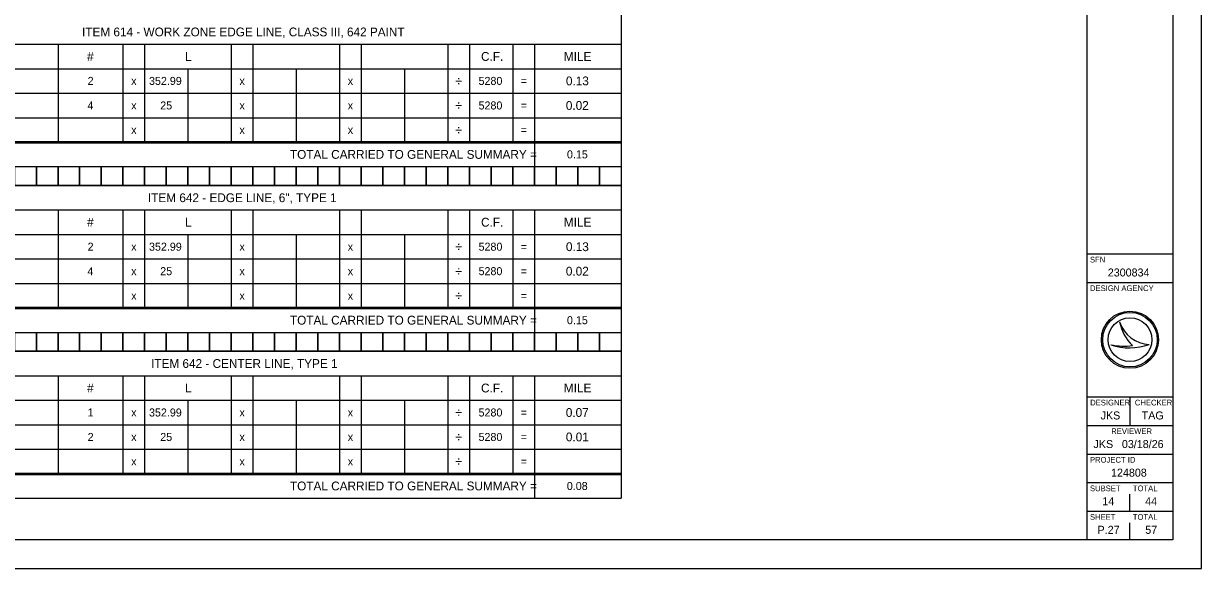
# Model space of a CAD drawing. Extents: x 0 to 34, y 0 to 22.
# Drawn here: x 13.4 to 34, y 0 to 9.53 of the extents above; entities that cross this region are included whole.
import ezdxf

# ---------------------------------------------------------------- set-up
doc = ezdxf.new("R2010")
doc.units = 0
for name, color, linetype in [('Default', 7, 'Continuous'), ('SH_Border', 7, 'Continuous'), ('SH_Cut_Line', 7, 'Continuous'), ('SH_Data', 7, 'Continuous')]:
    doc.layers.add(name, color=color, linetype=linetype)

msp = doc.modelspace()

# ---------------------------------------------------------------- linework, layer by layer
at = {"layer": 'Default'}
for p, q in [((23.849, 10.364), (23.849, 7.443)), ((10.59, 9.167), (23.849, 9.167)), ((14, 9.167), (14, 7.465)), ((15.136, 9.167), (15.136, 7.465)), ((15.515, 9.167), (15.515, 7.465)), ((17.03, 9.167), (17.03, 7.465)), ((17.409, 9.167), (17.409, 7.465)), ((18.924, 9.167), (18.924, 7.465)), ((19.303, 9.167), (19.303, 7.465)), ((20.818, 9.167), (20.818, 7.465)), ((21.197, 9.167), (21.197, 7.465)), ((21.955, 9.167), (21.955, 7.465)), ((22.334, 9.167), (22.334, 7.465)), ((10.59, 8.739), (23.849, 8.739)), ((16.272, 8.739), (16.272, 7.465)), ((18.167, 8.739), (18.167, 7.465)), ((20.061, 8.739), (20.061, 7.465)), ((10.59, 8.311), (23.849, 8.311)), ((10.59, 7.882), (23.849, 7.882)), ((10.59, 7.465), (23.849, 7.465)), ((10.59, 7.443), (23.849, 7.443)), ((22.334, 7.443), (22.334, 7.026)), ((23.849, 7.465), (23.849, 4.544)), ((10.59, 7.026), (23.849, 7.026)), ((10.59, 6.696), (23.849, 6.696)), ((10.59, 6.268), (23.849, 6.268)), ((14, 6.268), (14, 4.566)), ((15.136, 6.268), (15.136, 4.566)), ((15.515, 6.268), (15.515, 4.566)), ((17.03, 6.268), (17.03, 4.566)), ((17.409, 6.268), (17.409, 4.566)), ((18.924, 6.268), (18.924, 4.566)), ((19.303, 6.268), (19.303, 4.566)), ((20.818, 6.268), (20.818, 4.566)), ((21.197, 6.268), (21.197, 4.566)), ((21.955, 6.268), (21.955, 4.566)), ((22.334, 6.268), (22.334, 4.566)), ((10.59, 5.84), (23.849, 5.84)), ((16.272, 5.84), (16.272, 4.566)), ((18.167, 5.84), (18.167, 4.566)), ((20.061, 5.84), (20.061, 4.566)), ((10.59, 5.412), (23.849, 5.412)), ((10.59, 4.983), (23.849, 4.983)), ((10.59, 4.566), (23.849, 4.566)), ((10.59, 4.544), (23.849, 4.544)), ((22.334, 4.544), (22.334, 4.127)), ((23.849, 4.566), (23.849, 1.645)), ((10.59, 4.127), (23.849, 4.127)), ((10.59, 3.798), (23.849, 3.798)), ((10.59, 3.369), (23.849, 3.369)), ((14, 3.369), (14, 1.667)), ((15.136, 3.369), (15.136, 1.667)), ((15.515, 3.369), (15.515, 1.667)), ((17.03, 3.369), (17.03, 1.667)), ((17.409, 3.369), (17.409, 1.667)), ((18.924, 3.369), (18.924, 1.667)), ((19.303, 3.369), (19.303, 1.667)), ((20.818, 3.369), (20.818, 1.667)), ((21.197, 3.369), (21.197, 1.667)), ((21.955, 3.369), (21.955, 1.667)), ((22.334, 3.369), (22.334, 1.667)), ((10.59, 2.941), (23.849, 2.941)), ((16.272, 2.941), (16.272, 1.667)), ((18.167, 2.941), (18.167, 1.667)), ((20.061, 2.941), (20.061, 1.667)), ((10.59, 2.513), (23.849, 2.513)), ((10.59, 2.085), (23.849, 2.085)), ((10.59, 1.667), (23.849, 1.667)), ((23.849, 1.667), (23.849, 1.228)), ((10.59, 1.645), (23.849, 1.645)), ((22.334, 1.645), (22.334, 1.228)), ((10.59, 1.228), (23.849, 1.228))]:
    msp.add_line(p, q, dxfattribs=at)
for points in [[(13.242, 7.026), (13.621, 7.026), (13.621, 6.696), (13.242, 6.696)], [(13.621, 7.026), (14, 7.026), (14, 6.696), (13.621, 6.696)], [(14, 7.026), (14.378, 7.026), (14.378, 6.696), (14, 6.696)], [(14.378, 7.026), (14.757, 7.026), (14.757, 6.696), (14.378, 6.696)], [(14.757, 7.026), (15.136, 7.026), (15.136, 6.696), (14.757, 6.696)], [(15.136, 7.026), (15.515, 7.026), (15.515, 6.696), (15.136, 6.696)], [(15.515, 7.026), (15.894, 7.026), (15.894, 6.696), (15.515, 6.696)], [(15.894, 7.026), (16.272, 7.026), (16.272, 6.696), (15.894, 6.696)], [(16.272, 7.026), (16.651, 7.026), (16.651, 6.696), (16.272, 6.696)], [(16.651, 7.026), (17.03, 7.026), (17.03, 6.696), (16.651, 6.696)], [(17.03, 7.026), (17.409, 7.026), (17.409, 6.696), (17.03, 6.696)], [(17.409, 7.026), (17.788, 7.026), (17.788, 6.696), (17.409, 6.696)], [(17.788, 7.026), (18.167, 7.026), (18.167, 6.696), (17.788, 6.696)], [(18.167, 7.026), (18.545, 7.026), (18.545, 6.696), (18.167, 6.696)], [(18.545, 7.026), (18.924, 7.026), (18.924, 6.696), (18.545, 6.696)], [(18.924, 7.026), (19.303, 7.026), (19.303, 6.696), (18.924, 6.696)], [(19.303, 7.026), (19.682, 7.026), (19.682, 6.696), (19.303, 6.696)], [(19.682, 7.026), (20.061, 7.026), (20.061, 6.696), (19.682, 6.696)], [(20.061, 7.026), (20.44, 7.026), (20.44, 6.696), (20.061, 6.696)], [(20.44, 7.026), (20.818, 7.026), (20.818, 6.696), (20.44, 6.696)], [(20.818, 7.026), (21.197, 7.026), (21.197, 6.696), (20.818, 6.696)], [(21.197, 7.026), (21.576, 7.026), (21.576, 6.696), (21.197, 6.696)], [(21.576, 7.026), (21.955, 7.026), (21.955, 6.696), (21.576, 6.696)], [(21.955, 7.026), (22.334, 7.026), (22.334, 6.696), (21.955, 6.696)], [(22.334, 7.026), (22.712, 7.026), (22.712, 6.696), (22.334, 6.696)], [(22.712, 7.026), (23.091, 7.026), (23.091, 6.696), (22.712, 6.696)], [(23.091, 7.026), (23.47, 7.026), (23.47, 6.696), (23.091, 6.696)], [(23.47, 7.026), (23.849, 7.026), (23.849, 6.696), (23.47, 6.696)], [(13.242, 4.127), (13.621, 4.127), (13.621, 3.798), (13.242, 3.798)], [(13.621, 4.127), (14, 4.127), (14, 3.798), (13.621, 3.798)], [(14, 4.127), (14.378, 4.127), (14.378, 3.798), (14, 3.798)], [(14.378, 4.127), (14.757, 4.127), (14.757, 3.798), (14.378, 3.798)], [(14.757, 4.127), (15.136, 4.127), (15.136, 3.798), (14.757, 3.798)], [(15.136, 4.127), (15.515, 4.127), (15.515, 3.798), (15.136, 3.798)], [(15.515, 4.127), (15.894, 4.127), (15.894, 3.798), (15.515, 3.798)], [(15.894, 4.127), (16.272, 4.127), (16.272, 3.798), (15.894, 3.798)], [(16.272, 4.127), (16.651, 4.127), (16.651, 3.798), (16.272, 3.798)], [(16.651, 4.127), (17.03, 4.127), (17.03, 3.798), (16.651, 3.798)], [(17.03, 4.127), (17.409, 4.127), (17.409, 3.798), (17.03, 3.798)], [(17.409, 4.127), (17.788, 4.127), (17.788, 3.798), (17.409, 3.798)], [(17.788, 4.127), (18.167, 4.127), (18.167, 3.798), (17.788, 3.798)], [(18.167, 4.127), (18.545, 4.127), (18.545, 3.798), (18.167, 3.798)], [(18.545, 4.127), (18.924, 4.127), (18.924, 3.798), (18.545, 3.798)], [(18.924, 4.127), (19.303, 4.127), (19.303, 3.798), (18.924, 3.798)], [(19.303, 4.127), (19.682, 4.127), (19.682, 3.798), (19.303, 3.798)], [(19.682, 4.127), (20.061, 4.127), (20.061, 3.798), (19.682, 3.798)], [(20.061, 4.127), (20.44, 4.127), (20.44, 3.798), (20.061, 3.798)], [(20.44, 4.127), (20.818, 4.127), (20.818, 3.798), (20.44, 3.798)], [(20.818, 4.127), (21.197, 4.127), (21.197, 3.798), (20.818, 3.798)], [(21.197, 4.127), (21.576, 4.127), (21.576, 3.798), (21.197, 3.798)], [(21.576, 4.127), (21.955, 4.127), (21.955, 3.798), (21.576, 3.798)], [(21.955, 4.127), (22.334, 4.127), (22.334, 3.798), (21.955, 3.798)], [(22.334, 4.127), (22.712, 4.127), (22.712, 3.798), (22.334, 3.798)], [(22.712, 4.127), (23.091, 4.127), (23.091, 3.798), (22.712, 3.798)], [(23.091, 4.127), (23.47, 4.127), (23.47, 3.798), (23.091, 3.798)], [(23.47, 4.127), (23.849, 4.127), (23.849, 3.798), (23.47, 3.798)]]:
    msp.add_lwpolyline(points, close=True, dxfattribs=at)
at = {"layer": 'SH_Border'}
for p, q in [((32, 0.5), (32, 21.5)), ((32, 5.5), (33.5, 5.5)), ((32, 5), (33.5, 5)), ((32, 3), (33.5, 3)), ((32.75, 3), (32.75, 2.5)), ((32, 2.5), (33.5, 2.5)), ((32, 2), (33.5, 2)), ((32, 1.5), (33.5, 1.5)), ((32, 1), (33.5, 1))]:
    msp.add_line(p, q, dxfattribs=at)
msp.add_lwpolyline([(1.5, 21.5), (33.5, 21.5), (33.5, 0.5), (1.5, 0.5)], close=True, dxfattribs=at)
at = {"layer": 'SH_Cut_Line'}
msp.add_lwpolyline([(0, 0), (34, 0), (34, 22), (0, 22)], close=True, dxfattribs=at)
at = {"layer": 'SH_Data'}
for p, q in [((32.567, 4.31), (32.567, 4.31)), ((32.75, 4), (32.75, 4)), ((33.087, 3.919), (33.087, 3.919)), ((32.417, 3.91), (32.417, 3.91)), ((32.75, 1), (32.75, 1.3)), ((32.375, 0.675), (32.375, 0.675)), ((32.75, 0.5), (32.75, 0.8))]:
    msp.add_line(p, q, dxfattribs=at)
for radius in [0.5, 0.477, 0.477, 0.382]:
    msp.add_circle((32.75, 4), radius, dxfattribs=at)
for centre, radius, start, end in [((33.116, 4.498), 0.58, 198.9257, 198.9319), ((33.347, 4.47), 0.796, 191.6379, 191.6421), ((33.116, 4.498), 0.58, 198.9319, 267.1657), ((33.347, 4.47), 0.796, 191.6421, 226.0947), ((32.739, 4.87), 1.013, 251.4576, 290.0832), ((32.648, 5.154), 1.266, 259.4964, 259.4995), ((32.739, 4.87), 1.013, 251.4527, 251.4576), ((32.648, 5.154), 1.266, 259.4995, 276.6672)]:
    msp.add_arc(centre, radius, start, end, dxfattribs=at)

# ---------------------------------------------------------------- texts
at = {"layer": 'Default'}
for s, height, p in [('ITEM 614 - WORK ZONE EDGE LINE, CLASS III, 642 PAINT', 0.154, (14.42, 9.304)), ('#', 0.154, (14.509, 8.876)), ('L', 0.154, (16.222, 8.876)), ('C.F.', 0.154, (21.399, 8.876)), ('MILE', 0.154, (22.848, 8.876)), ('2', 0.14, (14.518, 8.455)), ('x', 0.14, (15.28, 8.455)), ('352.99', 0.14, (15.592, 8.455)), ('x', 0.14, (17.174, 8.455)), ('x', 0.14, (19.068, 8.455)), ('÷', 0.168, (20.946, 8.441)), ('5280', 0.14, (21.356, 8.455)), ('=', 0.14, (22.094, 8.455)), ('0.13', 0.154, (22.884, 8.448)), ('4', 0.14, (14.515, 8.026)), ('x', 0.14, (15.28, 8.026)), ('25', 0.14, (15.788, 8.026)), ('x', 0.14, (17.174, 8.026)), ('x', 0.14, (19.068, 8.026)), ('÷', 0.168, (20.946, 8.012)), ('5280', 0.14, (21.356, 8.026)), ('=', 0.14, (22.094, 8.026)), ('0.02', 0.154, (22.883, 8.019)), ('x', 0.14, (15.28, 7.598)), ('x', 0.14, (17.174, 7.598)), ('x', 0.14, (19.068, 7.598)), ('÷', 0.168, (20.946, 7.584)), ('=', 0.14, (22.094, 7.598)), ('TOTAL CARRIED TO GENERAL SUMMARY =', 0.154, (18.057, 7.163)), ('0.15', 0.14, (22.902, 7.17)), ('ITEM 642 - EDGE LINE, 6", TYPE 1', 0.154, (15.573, 6.405)), ('#', 0.154, (14.509, 5.977)), ('L', 0.154, (16.222, 5.977)), ('C.F.', 0.154, (21.399, 5.977)), ('MILE', 0.154, (22.848, 5.977)), ('2', 0.14, (14.518, 5.556)), ('x', 0.14, (15.28, 5.556)), ('352.99', 0.14, (15.592, 5.556)), ('x', 0.14, (17.174, 5.556)), ('x', 0.14, (19.068, 5.556)), ('÷', 0.168, (20.946, 5.542)), ('5280', 0.14, (21.356, 5.556)), ('=', 0.14, (22.094, 5.556)), ('0.13', 0.154, (22.884, 5.549)), ('4', 0.14, (14.515, 5.128)), ('x', 0.14, (15.28, 5.128)), ('25', 0.14, (15.788, 5.128)), ('x', 0.14, (17.174, 5.128)), ('x', 0.14, (19.068, 5.128)), ('÷', 0.168, (20.946, 5.114)), ('5280', 0.14, (21.356, 5.128)), ('=', 0.14, (22.094, 5.128)), ('0.02', 0.154, (22.883, 5.121)), ('x', 0.14, (15.28, 4.699)), ('x', 0.14, (17.174, 4.699)), ('x', 0.14, (19.068, 4.699)), ('÷', 0.168, (20.946, 4.685)), ('=', 0.14, (22.094, 4.699)), ('TOTAL CARRIED TO GENERAL SUMMARY =', 0.154, (18.057, 4.264)), ('0.15', 0.14, (22.902, 4.271)), ('ITEM 642 - CENTER LINE, TYPE 1', 0.154, (15.628, 3.506)), ('#', 0.154, (14.509, 3.078)), ('L', 0.154, (16.222, 3.078)), ('C.F.', 0.154, (21.399, 3.078)), ('MILE', 0.154, (22.848, 3.078)), ('1', 0.14, (14.518, 2.657)), ('x', 0.14, (15.28, 2.657)), ('352.99', 0.14, (15.592, 2.657)), ('x', 0.14, (17.174, 2.657)), ('x', 0.14, (19.068, 2.657)), ('÷', 0.168, (20.946, 2.643)), ('5280', 0.14, (21.356, 2.657)), ('=', 0.14, (22.094, 2.657)), ('0.07', 0.154, (22.882, 2.65)), ('2', 0.14, (14.518, 2.229)), ('x', 0.14, (15.28, 2.229)), ('25', 0.14, (15.788, 2.229)), ('x', 0.14, (17.174, 2.229)), ('x', 0.14, (19.068, 2.229)), ('÷', 0.168, (20.946, 2.215)), ('5280', 0.14, (21.356, 2.229)), ('=', 0.14, (22.094, 2.229)), ('0.01', 0.154, (22.883, 2.222)), ('x', 0.14, (15.28, 1.801)), ('x', 0.14, (17.174, 1.801)), ('x', 0.14, (19.068, 1.801)), ('÷', 0.168, (20.946, 1.787)), ('=', 0.14, (22.094, 1.801)), ('TOTAL CARRIED TO GENERAL SUMMARY =', 0.154, (18.057, 1.365)), ('0.08', 0.14, (22.9, 1.372))]:
    msp.add_text(s, height=height, dxfattribs=at).set_placement(p)
at = {"layer": 'SH_Data'}
for s, height, p in [('SFN', 0.1, (32.05, 5.35)), ('2300834', 0.14, (32.362, 5.105)), ('DESIGN AGENCY', 0.1, (32.05, 4.85)), ('DESIGNER', 0.1, (32.054, 2.85)), ('CHECKER', 0.1, (32.835, 2.85)), ('JKS', 0.14, (32.237, 2.605)), ('TAG', 0.14, (32.955, 2.605)), ('REVIEWER', 0.1, (32.422, 2.35)), ('JKS', 0.14, (32.112, 2.105)), ('03/18/26', 0.14, (32.609, 2.105)), ('PROJECT ID', 0.1, (32.05, 1.85)), ('124808', 0.14, (32.419, 1.605)), ('SUBSET', 0.1, (32.05, 1.35)), ('TOTAL', 0.1, (32.8, 1.35)), ('14', 0.14, (32.266, 1.105)), ('44', 0.14, (33.016, 1.105)), ('SHEET', 0.1, (32.05, 0.85)), ('TOTAL', 0.1, (32.8, 0.85)), ('P.27', 0.14, (32.183, 0.605)), ('57', 0.14, (33.018, 0.605))]:
    msp.add_text(s, height=height, dxfattribs=at).set_placement(p)

doc.saveas('drawing.dxf')
